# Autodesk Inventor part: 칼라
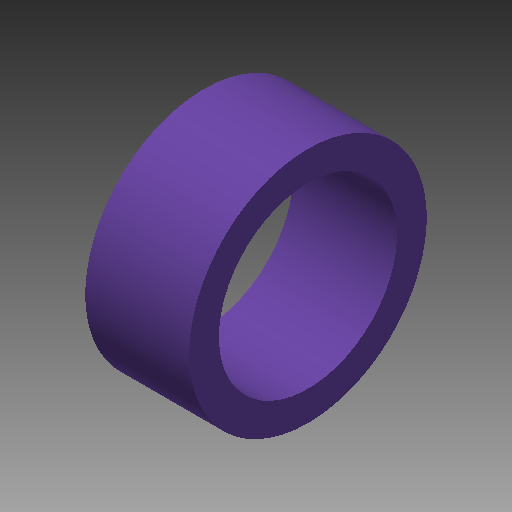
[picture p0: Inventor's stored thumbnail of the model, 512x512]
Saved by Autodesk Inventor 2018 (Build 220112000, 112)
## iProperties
Created: 2020-04
Part Number: 칼라
Material: 강철, 연강
Document SubType Name: Modeling
Designer: mduedu
Density: 7.86 g/cm^3
Mass: 4.83981 g
Surface Area: 7.91681 cm^2
Volume: 0.615752 cm^3
Appearance: 보라색
Author: mduedu
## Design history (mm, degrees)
sketch "스케치1"
  geometry: C1 r 8 at (0, 0); C2 r 6 at (0, 0); 1 further point
  constraints: 2 centre point, 2 coincident
  dimensions: "d0" = 16 diameter of C1; "d1" = 12 diameter of C2
extrude "돌출1" new body sketch "스케치1" distance "d2" = 7; taper "d3" = 0 deg
node "솔리드1"
